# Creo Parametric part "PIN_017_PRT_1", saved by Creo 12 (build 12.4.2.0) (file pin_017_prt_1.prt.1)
Units: Custom; MM, KILOGRAM, SECS

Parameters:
  PTC_WM_ITERATION = "0"
  PTC_WM_VERSION = "-.0"
  PTC_WM_LIFECYCLE_STATE = "In Work"
  PTC_WM_LIFECYCLE = "MO_CADDocument"
  PTC_WM_CREATED_BY = "Maximilian Roepper (Z0017RMS: MO)"
  PTC_WM_CREATED_ON = "18-Sep-26 11:36:42 AM"
  PTC_WM_MODIFIED_BY = "Maximilian Roepper (Z0017RMS: MO)"
  PTC_WM_MODIFIED_ON = "18-Sep-26 11:36:46 AM"
  PDMLINKNUMBER = "PDM000071454760"
  PTC_WM_NAME = "pin_017_prt_1.prt"
  PTC_WM_NUMBER = "PDM000071454760"

Other parameters: WEIGHT, WEIGHT_FACTOR, WEIGHT_ADD, _MASS_TEMP, _DIFF_TEMP, MC_ERRORS, SUPPLIER

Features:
  1. coordinate system
  2. datum plane "PRT_YZ"
  3. datum plane "PRT_XY"
  4. datum plane "PRT_XZ"
  5. coordinate system
  6. datum axis
  7. datum axis
  8. datum axis
  9. coordinate system
  10. imported feature
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
Other named items: PRT, SIEMENS_MO, DRW_VIEW_ORG, PRT_X, PRT_Y, PRT_Z, CS0, ROUGH_GROB

Layers: 00_STD_CSYS-KSYS, 01_STD_PLANES-EBENEN, 02_STD_AXES-ACHSEN, 03_STD_CSYS-KSYS, 24_IMPORT_FEAT-IMPORT_KE

Surfaces: 9 plane, 1 cylinder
